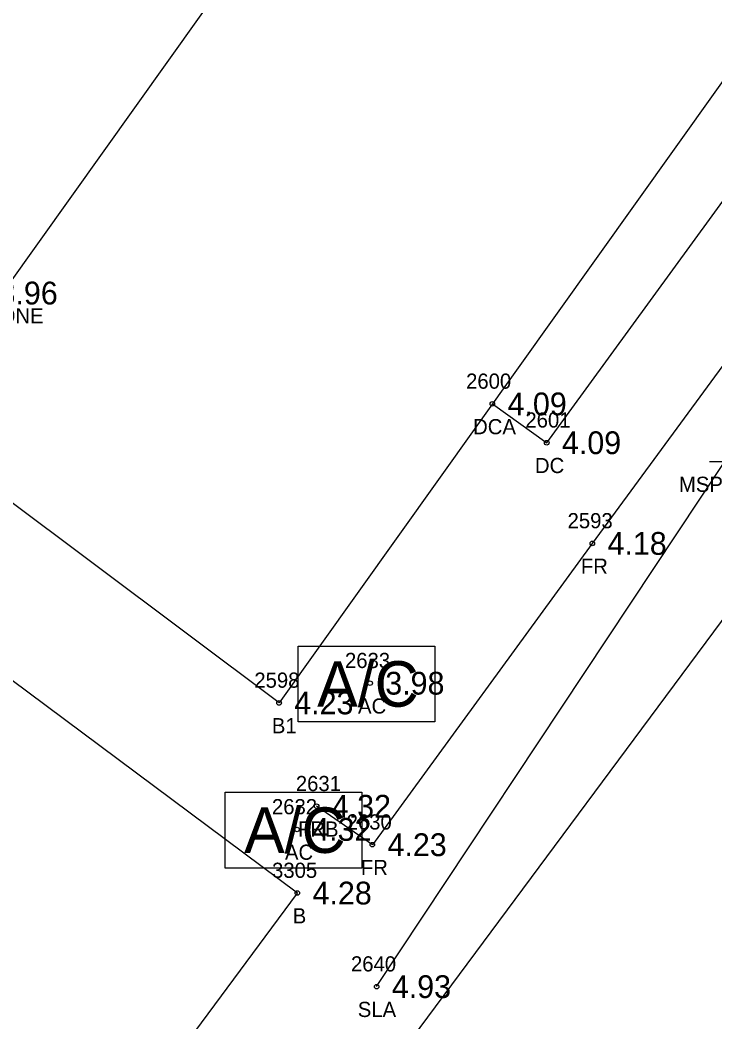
# Model space of a CAD drawing. Extents: x 2608598 to 2610682, y 641451 to 643526.
# Drawn here: x 2610061 to 2610106.8, y 641972.3 to 642038.3 of the extents above; entities that cross this region are included whole.
import ezdxf

# ---------------------------------------------------------------- set-up
doc = ezdxf.new("R2010")
doc.units = 0
for name, color, linetype in [('RD_EX_Bldg', 7, 'Continuous'), ('RD_EX_Bldg_txCode', 7, 'Continuous'), ('RD_EX_BldgApp', 7, 'Continuous'), ('RD_EX_BldgApp_txCode', 7, 'Continuous'), ('RD_EX_Conc', 7, 'Continuous'), ('RD_EX_Conc_txCode', 7, 'Continuous'), ('RD_EX_Fence_Other', 7, 'Continuous'), ('RD_EX_Fence_Other_txCode', 7, 'Continuous'), ('RD_EX_Misc', 7, 'Continuous'), ('RD_EX_Misc_txCode', 7, 'Continuous'), ('RD_EX_TX_Bldg_ELEV', 7, 'Continuous'), ('RD_EX_TX_BldgApp_ELEV', 7, 'Continuous'), ('RD_EX_TX_Conc_ELEV', 7, 'Continuous'), ('RD_EX_TX_Fence_Other_ELEV', 7, 'Continuous'), ('RD_EX_TX_Misc_ELEV', 7, 'Continuous'), ('RD_EX_TX_VEG_ELEV', 7, 'Continuous'), ('RD_EX_VEG', 7, 'Continuous'), ('RD_EX_VEG_txCode', 7, 'Continuous'), ('RD_SMD_Locator', 7, 'Continuous')]:
    doc.layers.add(name, color=color, linetype=linetype)

msp = doc.modelspace()

# ---------------------------------------------------------------- linework, layer by layer
at = {"layer": 'RD_EX_Bldg'}
for points in [[(2610053.59, 642011.651), (2610094.327, 642068.736), (2610111.856, 642055.619), (2610105.498, 642045.99), (2610112.03, 642040.97), (2610078.047, 641993.35), (2610053.59, 642011.651)], [(2610074.75, 641955.019), (2610121.892, 642018.487), (2610144.774, 642001.166), (2610097.632, 641937.698), (2610074.75, 641955.019)], [(2610055.591, 641998.422), (2610028.78, 641961.419), (2610024.204, 641964.927), (2610014.464, 641951.932), (2610030.087, 641940.651), (2610042.735, 641931.519), (2610079.254, 641980.823), (2610055.591, 641998.422)]]:
    msp.add_lwpolyline(points, dxfattribs=at)
at = {"layer": 'RD_EX_BldgApp'}
for points in [[(2610079.312, 641992.097), (2610079.312, 641997.097), (2610088.312, 641997.097), (2610088.312, 641992.097)], [(2610074.497, 641982.463), (2610074.497, 641987.463), (2610083.497, 641987.463), (2610083.497, 641982.463)]]:
    msp.add_lwpolyline(points, close=True, dxfattribs=at)
at = {"layer": 'RD_EX_Conc'}
msp.add_lwpolyline([(2610092.106, 642013.051), (2610095.692, 642010.492), (2610113.596, 642035.061), (2610109.837, 642037.898)], dxfattribs=at)
at = {"layer": 'RD_EX_Fence_Other'}
msp.add_lwpolyline([(2610147.084, 642069.782), (2610125.734, 642040.697), (2610098.694, 642003.858), (2610084.195, 641984.008), (2610080.523, 641986.54)], dxfattribs=at)
at = {"layer": 'RD_EX_Misc'}
msp.add_line((2610106.421, 642009.254), (2610116.421, 642009.254), dxfattribs=at)
at = {"layer": 'RD_EX_VEG'}
msp.add_lwpolyline([(2610084.48, 641974.656), (2610118, 642025.172), (2610127.094, 642025.609)], dxfattribs=at)
at = {"layer": 'RD_SMD_Locator'}
for centre in [(2610092.106, 642013.051), (2610095.692, 642010.492), (2610098.694, 642003.858), (2610084.046, 641994.648), (2610078.047, 641993.35), (2610080.523, 641986.54), (2610079.231, 641985.014), (2610084.195, 641984.008), (2610079.254, 641980.823), (2610084.48, 641974.656)]:
    msp.add_circle(centre, 0.15, dxfattribs=at)

# ---------------------------------------------------------------- texts
at = {"layer": 'RD_EX_Bldg_txCode'}
for s, p in [('2598', (2610076.417, 641994.35)), ('B1', (2610077.574, 641991.35)), ('3305', (2610077.585, 641981.823)), ('B', (2610078.947, 641978.823))]:
    msp.add_text(s, height=1, dxfattribs=at).set_placement(p)
at = {"layer": 'RD_EX_BldgApp'}
for p in [(2610080.557, 641993.1), (2610075.743, 641983.466)]:
    msp.add_text('A/C', height=3, dxfattribs=at).set_placement(p)
at = {"layer": 'RD_EX_BldgApp_txCode'}
for s, p in [('2633', (2610082.392, 641995.648)), ('AC', (2610083.251, 641992.648)), ('2632', (2610077.578, 641986.014)), ('AC', (2610078.436, 641983.014))]:
    msp.add_text(s, height=1, dxfattribs=at).set_placement(p)
at = {"layer": 'RD_EX_Conc_txCode'}
for s, p in [('2600', (2610090.374, 642014.051)), ('2601', (2610094.282, 642011.492)), ('DCA', (2610090.838, 642011.051)), ('DC', (2610094.912, 642008.492))]:
    msp.add_text(s, height=1, dxfattribs=at).set_placement(p)
at = {"layer": 'RD_EX_Fence_Other_txCode'}
for s, p in [('2593', (2610097.064, 642004.858)), ('FR', (2610097.938, 642001.858)), ('2631', (2610079.153, 641987.54)), ('2630', (2610082.502, 641985.008)), ('FRB', (2610079.295, 641984.54)), ('FR', (2610083.439, 641982.008))]:
    msp.add_text(s, height=1, dxfattribs=at).set_placement(p)
at = {"layer": 'RD_EX_Misc_txCode'}
for s, p in [('WA 1STONE', (2610054.655, 642018.354)), ('MSP WATERHEATER', (2610104.405, 642007.254))]:
    msp.add_text(s, height=1, dxfattribs=at).set_placement(p)
at = {"layer": 'RD_EX_TX_Bldg_ELEV'}
for s, p in [('4.23', (2610079.047, 641992.6)), ('4.28', (2610080.254, 641980.073))]:
    msp.add_text(s, height=1.5, dxfattribs=at).set_placement(p)
at = {"layer": 'RD_EX_TX_BldgApp_ELEV'}
for s, p in [('3.98', (2610085.046, 641993.898)), ('4.32', (2610080.231, 641984.264))]:
    msp.add_text(s, height=1.5, dxfattribs=at).set_placement(p)
at = {"layer": 'RD_EX_TX_Conc_ELEV'}
for p in [(2610093.106, 642012.301), (2610096.692, 642009.742)]:
    msp.add_text('4.09', height=1.5, dxfattribs=at).set_placement(p)
at = {"layer": 'RD_EX_TX_Fence_Other_ELEV'}
for s, p in [('4.18', (2610099.694, 642003.108)), ('4.32', (2610081.523, 641985.79)), ('4.23', (2610085.195, 641983.258))]:
    msp.add_text(s, height=1.5, dxfattribs=at).set_placement(p)
at = {"layer": 'RD_EX_TX_Misc_ELEV'}
msp.add_text('3.96', height=1.5, dxfattribs=at).set_placement((2610059.557, 642019.604))
at = {"layer": 'RD_EX_TX_VEG_ELEV'}
msp.add_text('4.93', height=1.5, dxfattribs=at).set_placement((2610085.48, 641973.906))
at = {"layer": 'RD_EX_VEG_txCode'}
for s, p in [('2640', (2610082.787, 641975.656)), ('SLA', (2610083.236, 641972.656))]:
    msp.add_text(s, height=1, dxfattribs=at).set_placement(p)

doc.saveas('drawing.dxf')
